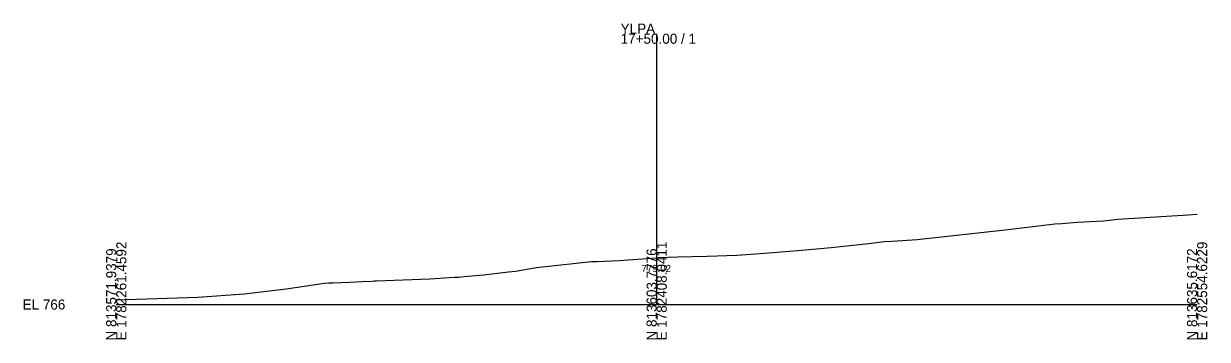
# Model space of a CAD drawing. Extents: x -76 to 1303, y -10 to 9544.
# Drawn here: x -25.7 to 302.8, y 7490.3 to 7578.1 of the extents above; entities that cross this region are included whole.
import ezdxf

# ---------------------------------------------------------------- set-up
doc = ezdxf.new("R2010")
doc.units = 0
for name, color, linetype in [('Exist Cross Section Cell', 7, 'Continuous'), ('Exist XS Center Line Elevation Label', 7, 'Continuous'), ('Exist XS Ground Line', 7, 'Continuous')]:
    doc.layers.add(name, color=color, linetype=linetype)

msp = doc.modelspace()

# ---------------------------------------------------------------- linework, layer by layer
at = {"layer": 'Exist Cross Section Cell'}
for p, q in [((150, 7500), (150, 7575.3)), ((0, 7500), (150, 7500)), ((150, 7500), (300, 7500))]:
    msp.add_line(p, q, dxfattribs=at)
at = {"layer": 'Exist XS Ground Line'}
for p, q in [((274.06, 7523.28), (277.96, 7523.69)), ((277.96, 7523.69), (297.56, 7524.91)), ((297.56, 7524.91), (300, 7525.1)), ((222.26, 7518.12), (247.57, 7520.87)), ((247.57, 7520.87), (260.55, 7522.4)), ((260.55, 7522.4), (262.43, 7522.53)), ((262.43, 7522.53), (266.7, 7522.88)), ((266.7, 7522.88), (274.06, 7523.28)), ((198.4, 7515.82), (208.75, 7517)), ((208.75, 7517), (213.24, 7517.5)), ((213.24, 7517.5), (215.33, 7517.65)), ((215.33, 7517.65), (222.26, 7518.12)), ((164.05, 7513.47), (172.25, 7513.71)), ((172.25, 7513.71), (178.71, 7514.17)), ((178.71, 7514.17), (189.2, 7515.04)), ((189.2, 7515.04), (198.4, 7515.82)), ((110.8, 7509.27), (116.64, 7510.26)), ((116.64, 7510.26), (118.29, 7510.45)), ((118.29, 7510.45), (131.95, 7511.93)), ((131.95, 7511.93), (133.47, 7511.95)), ((133.47, 7511.95), (139.64, 7512.28)), ((139.64, 7512.28), (143.4, 7512.5)), ((143.4, 7512.5), (150, 7513.02)), ((150, 7513.02), (150.44, 7513.06)), ((150.44, 7513.06), (155.86, 7513.22)), ((155.86, 7513.22), (164.05, 7513.47)), ((72.22, 7506.57), (87.05, 7507.12)), ((87.05, 7507.12), (93.9, 7507.58)), ((93.9, 7507.58), (94.99, 7507.63)), ((94.99, 7507.63), (96.58, 7507.78)), ((96.58, 7507.78), (101.91, 7508.28)), ((101.91, 7508.28), (108.9, 7509.09)), ((108.9, 7509.09), (110.8, 7509.27)), ((35.48, 7502.98), (47.12, 7504.34)), ((47.12, 7504.34), (57.76, 7505.9)), ((57.76, 7505.9), (59.03, 7505.99)), ((59.03, 7505.99), (60.15, 7506.05)), ((60.15, 7506.05), (64.74, 7506.25)), ((64.74, 7506.25), (68.25, 7506.41)), ((68.25, 7506.41), (71, 7506.51)), ((71, 7506.51), (71.61, 7506.54)), ((71.61, 7506.54), (72.22, 7506.57)), ((0, 7501.29), (22.67, 7502.01)), ((22.67, 7502.01), (35.48, 7502.98))]:
    msp.add_line(p, q, dxfattribs=at)

# ---------------------------------------------------------------- texts
at = {"layer": 'Exist Cross Section Cell'}
for s, p in [('YLPA', (140, 7575.3)), ('17+50.00 / 1', (140, 7572.5)), ('EL 766', (-26, 7498.6))]:
    msp.add_text(s, height=2.8, dxfattribs=at).set_placement(p)
for s, p in [('E 1782261.4592', (2.8, 7490)), ('E 1782408.0411', (152.8, 7490)), ('E 1782554.6229', (302.8, 7490)), ('N 813571.9379', (0, 7490)), ('N 813603.7776', (150, 7490)), ('N 813635.6172', (300, 7490))]:
    msp.add_text(s, height=2.8, rotation=90, dxfattribs=at).set_placement(p)
at = {"layer": 'Exist XS Center Line Elevation Label'}
msp.add_text('779.02', height=2, dxfattribs=at).set_placement((145.79, 7509.02))

doc.saveas('drawing.dxf')
